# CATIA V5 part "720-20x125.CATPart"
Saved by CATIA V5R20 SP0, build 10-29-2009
Part number: 720-20x125
Definition: NONE
Nomenclature: 720-20x125
Source: Unknown
Description: 720-20x125
Bounding box of the stored display mesh (mm): x 0 to 125, y -10 to 10, z -10 to 10
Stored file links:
  C:\Users\Utente\Desktop\IO LAVORO\3D X SITO CF\X SITO\720\720-20x125.CATPart

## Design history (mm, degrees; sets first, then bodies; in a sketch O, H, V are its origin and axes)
Body1 "720-20x125" (main body)
  Solid1: solid without history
